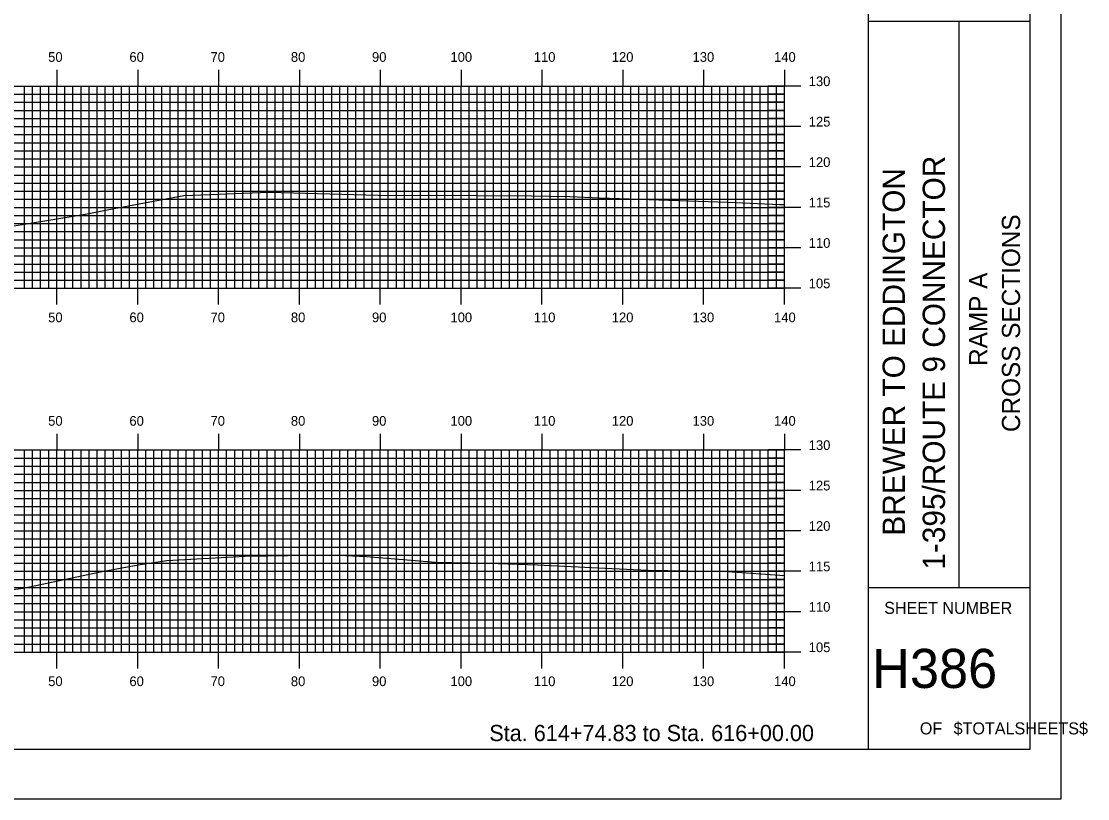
# Model space of a CAD drawing. Extents: x 844536 to 844879, y 363538 to 363758.
# Drawn here: x 844747.6 to 844879.5, y 363537.6 to 363633.7 of the extents above; entities that cross this region are included whole.
import ezdxf

# ---------------------------------------------------------------- set-up
doc = ezdxf.new("R2010")
doc.units = 0
for name, color, linetype in [('BORDER', 7, 'Continuous'), ('H_V ANNOTATION', 7, 'Continuous'), ('MAJOR', 7, 'Continuous'), ('MINOR', 7, 'Continuous'), ('PLOT BOUNDARY', 7, 'Continuous'), ('S_Roadway_Centerline', 7, 'Continuous')]:
    doc.layers.add(name, color=color, linetype=linetype)

msp = doc.modelspace()

# ---------------------------------------------------------------- linework, layer by layer
at = {"layer": 'BORDER'}
for p, q in [((844852.36, 363543.72), (844852.36, 363753.72)), ((844852.36, 363633.73), (844872.36, 363633.73)), ((844863.55, 363563.73), (844863.55, 363633.73)), ((844852.36, 363563.73), (844872.36, 363563.73))]:
    msp.add_line(p, q, dxfattribs=at)
msp.add_lwpolyline([(844552.36, 363543.72), (844872.36, 363543.72), (844872.36, 363753.72), (844552.36, 363753.72)], close=True, dxfattribs=at)
at = {"layer": 'MAJOR'}
for p, q in [((844751.96, 363627.73), (844751.96, 363625.72)), ((844761.96, 363627.73), (844761.96, 363625.72)), ((844771.96, 363627.73), (844771.96, 363625.72)), ((844781.96, 363627.73), (844781.96, 363625.72)), ((844791.96, 363627.73), (844791.96, 363625.72)), ((844801.96, 363627.73), (844801.96, 363625.72)), ((844811.96, 363627.73), (844811.96, 363625.72)), ((844821.96, 363627.73), (844821.96, 363625.72)), ((844831.96, 363627.73), (844831.96, 363625.72)), ((844841.96, 363627.73), (844841.96, 363625.72)), ((844561.96, 363625.72), (844841.96, 363625.72)), ((844561.96, 363625.72), (844841.96, 363625.72)), ((844751.96, 363600.72), (844751.96, 363625.72)), ((844761.96, 363600.72), (844761.96, 363625.72)), ((844771.96, 363600.72), (844771.96, 363625.72)), ((844781.96, 363600.72), (844781.96, 363625.72)), ((844791.96, 363600.72), (844791.96, 363625.72)), ((844801.96, 363600.72), (844801.96, 363625.72)), ((844811.96, 363600.72), (844811.96, 363625.72)), ((844821.96, 363600.72), (844821.96, 363625.72)), ((844831.96, 363600.72), (844831.96, 363625.72)), ((844843.97, 363625.72), (844839.96, 363625.72)), ((844841.96, 363600.72), (844841.96, 363625.72)), ((844841.96, 363600.72), (844841.96, 363625.72)), ((844561.96, 363620.72), (844841.96, 363620.72)), ((844843.97, 363620.72), (844839.96, 363620.72)), ((844561.96, 363615.72), (844841.96, 363615.72)), ((844843.97, 363615.72), (844839.96, 363615.72)), ((844561.96, 363610.72), (844841.96, 363610.72)), ((844843.97, 363610.72), (844839.96, 363610.72)), ((844561.96, 363605.72), (844841.96, 363605.72)), ((844843.97, 363605.72), (844839.96, 363605.72)), ((844561.96, 363600.72), (844841.96, 363600.72)), ((844561.96, 363600.72), (844841.96, 363600.72)), ((844751.96, 363598.72), (844751.96, 363600.72)), ((844761.96, 363598.72), (844761.96, 363600.72)), ((844771.96, 363598.72), (844771.96, 363600.72)), ((844781.96, 363598.72), (844781.96, 363600.72)), ((844791.96, 363598.72), (844791.96, 363600.72)), ((844801.96, 363598.72), (844801.96, 363600.72)), ((844811.96, 363598.72), (844811.96, 363600.72)), ((844821.96, 363598.72), (844821.96, 363600.72)), ((844831.96, 363598.72), (844831.96, 363600.72)), ((844843.97, 363600.72), (844839.96, 363600.72)), ((844841.96, 363598.72), (844841.96, 363600.72)), ((844751.96, 363582.73), (844751.96, 363580.72)), ((844761.96, 363582.73), (844761.96, 363580.72)), ((844771.96, 363582.73), (844771.96, 363580.72)), ((844781.96, 363582.73), (844781.96, 363580.72)), ((844791.96, 363582.73), (844791.96, 363580.72)), ((844801.96, 363582.73), (844801.96, 363580.72)), ((844811.96, 363582.73), (844811.96, 363580.72)), ((844821.96, 363582.73), (844821.96, 363580.72)), ((844831.96, 363582.73), (844831.96, 363580.72)), ((844841.96, 363582.73), (844841.96, 363580.72)), ((844561.96, 363580.72), (844841.96, 363580.72)), ((844561.96, 363580.72), (844841.96, 363580.72)), ((844751.96, 363555.72), (844751.96, 363580.72)), ((844761.96, 363555.72), (844761.96, 363580.72)), ((844771.96, 363555.72), (844771.96, 363580.72)), ((844781.96, 363555.72), (844781.96, 363580.72)), ((844791.96, 363555.72), (844791.96, 363580.72)), ((844801.96, 363555.72), (844801.96, 363580.72)), ((844811.96, 363555.72), (844811.96, 363580.72)), ((844821.96, 363555.72), (844821.96, 363580.72)), ((844831.96, 363555.72), (844831.96, 363580.72)), ((844843.97, 363580.72), (844839.96, 363580.72)), ((844841.96, 363555.72), (844841.96, 363580.72)), ((844841.96, 363555.72), (844841.96, 363580.72)), ((844561.96, 363575.72), (844841.96, 363575.72)), ((844843.97, 363575.72), (844839.96, 363575.72)), ((844561.96, 363570.72), (844841.96, 363570.72)), ((844843.97, 363570.72), (844839.96, 363570.72)), ((844561.96, 363565.72), (844841.96, 363565.72)), ((844843.97, 363565.72), (844839.96, 363565.72)), ((844561.96, 363560.72), (844841.96, 363560.72)), ((844843.97, 363560.72), (844839.96, 363560.72)), ((844561.96, 363555.72), (844841.96, 363555.72)), ((844561.96, 363555.72), (844841.96, 363555.72)), ((844751.96, 363553.72), (844751.96, 363555.72)), ((844761.96, 363553.72), (844761.96, 363555.72)), ((844771.96, 363553.72), (844771.96, 363555.72)), ((844781.96, 363553.72), (844781.96, 363555.72)), ((844791.96, 363553.72), (844791.96, 363555.72)), ((844801.96, 363553.72), (844801.96, 363555.72)), ((844811.96, 363553.72), (844811.96, 363555.72)), ((844821.96, 363553.72), (844821.96, 363555.72)), ((844831.96, 363553.72), (844831.96, 363555.72)), ((844843.97, 363555.72), (844839.96, 363555.72)), ((844841.96, 363553.72), (844841.96, 363555.72))]:
    msp.add_line(p, q, dxfattribs=at)
at = {"layer": 'MINOR'}
for p, q in [((844747.96, 363600.72), (844747.96, 363625.72)), ((844748.96, 363600.72), (844748.96, 363625.72)), ((844749.96, 363600.72), (844749.96, 363625.72)), ((844750.96, 363600.72), (844750.96, 363625.72)), ((844752.96, 363600.72), (844752.96, 363625.72)), ((844753.96, 363600.72), (844753.96, 363625.72)), ((844754.96, 363600.72), (844754.96, 363625.72)), ((844755.96, 363600.72), (844755.96, 363625.72)), ((844756.96, 363600.72), (844756.96, 363625.72)), ((844757.96, 363600.72), (844757.96, 363625.72)), ((844758.96, 363600.72), (844758.96, 363625.72)), ((844759.96, 363600.72), (844759.96, 363625.72)), ((844760.96, 363600.72), (844760.96, 363625.72)), ((844762.96, 363600.72), (844762.96, 363625.72)), ((844763.96, 363600.72), (844763.96, 363625.72)), ((844764.96, 363600.72), (844764.96, 363625.72)), ((844765.96, 363600.72), (844765.96, 363625.72)), ((844766.96, 363600.72), (844766.96, 363625.72)), ((844767.96, 363600.72), (844767.96, 363625.72)), ((844768.96, 363600.72), (844768.96, 363625.72)), ((844769.96, 363600.72), (844769.96, 363625.72)), ((844770.96, 363600.72), (844770.96, 363625.72)), ((844772.96, 363600.72), (844772.96, 363625.72)), ((844773.96, 363600.72), (844773.96, 363625.72)), ((844774.96, 363600.72), (844774.96, 363625.72)), ((844775.96, 363600.72), (844775.96, 363625.72)), ((844776.96, 363600.72), (844776.96, 363625.72)), ((844777.96, 363600.72), (844777.96, 363625.72)), ((844778.96, 363600.72), (844778.96, 363625.72)), ((844779.96, 363600.72), (844779.96, 363625.72)), ((844780.96, 363600.72), (844780.96, 363625.72)), ((844782.96, 363600.72), (844782.96, 363625.72)), ((844783.96, 363600.72), (844783.96, 363625.72)), ((844784.96, 363600.72), (844784.96, 363625.72)), ((844785.96, 363600.72), (844785.96, 363625.72)), ((844786.96, 363600.72), (844786.96, 363625.72)), ((844787.96, 363600.72), (844787.96, 363625.72)), ((844788.96, 363600.72), (844788.96, 363625.72)), ((844789.96, 363600.72), (844789.96, 363625.72)), ((844790.96, 363600.72), (844790.96, 363625.72)), ((844792.96, 363600.72), (844792.96, 363625.72)), ((844793.96, 363600.72), (844793.96, 363625.72)), ((844794.96, 363600.72), (844794.96, 363625.72)), ((844795.96, 363600.72), (844795.96, 363625.72)), ((844796.96, 363600.72), (844796.96, 363625.72)), ((844797.96, 363600.72), (844797.96, 363625.72)), ((844798.96, 363600.72), (844798.96, 363625.72)), ((844799.96, 363600.72), (844799.96, 363625.72)), ((844800.96, 363600.72), (844800.96, 363625.72)), ((844802.96, 363600.72), (844802.96, 363625.72)), ((844803.96, 363600.72), (844803.96, 363625.72)), ((844804.96, 363600.72), (844804.96, 363625.72)), ((844805.96, 363600.72), (844805.96, 363625.72)), ((844806.96, 363600.72), (844806.96, 363625.72)), ((844807.96, 363600.72), (844807.96, 363625.72)), ((844808.96, 363600.72), (844808.96, 363625.72)), ((844809.96, 363600.72), (844809.96, 363625.72)), ((844810.96, 363600.72), (844810.96, 363625.72)), ((844812.96, 363600.72), (844812.96, 363625.72)), ((844813.96, 363600.72), (844813.96, 363625.72)), ((844814.96, 363600.72), (844814.96, 363625.72)), ((844815.96, 363600.72), (844815.96, 363625.72)), ((844816.96, 363600.72), (844816.96, 363625.72)), ((844817.96, 363600.72), (844817.96, 363625.72)), ((844818.96, 363600.72), (844818.96, 363625.72)), ((844819.96, 363600.72), (844819.96, 363625.72)), ((844820.96, 363600.72), (844820.96, 363625.72)), ((844822.96, 363600.72), (844822.96, 363625.72)), ((844823.96, 363600.72), (844823.96, 363625.72)), ((844824.96, 363600.72), (844824.96, 363625.72)), ((844825.96, 363600.72), (844825.96, 363625.72)), ((844826.96, 363600.72), (844826.96, 363625.72)), ((844827.96, 363600.72), (844827.96, 363625.72)), ((844828.96, 363600.72), (844828.96, 363625.72)), ((844829.96, 363600.72), (844829.96, 363625.72)), ((844830.96, 363600.72), (844830.96, 363625.72)), ((844832.96, 363600.72), (844832.96, 363625.72)), ((844833.96, 363600.72), (844833.96, 363625.72)), ((844834.96, 363600.72), (844834.96, 363625.72)), ((844835.96, 363600.72), (844835.96, 363625.72)), ((844836.96, 363600.72), (844836.96, 363625.72)), ((844837.96, 363600.72), (844837.96, 363625.72)), ((844838.96, 363600.72), (844838.96, 363625.72)), ((844839.96, 363600.72), (844839.96, 363625.72)), ((844840.96, 363600.72), (844840.96, 363625.72)), ((844561.96, 363624.72), (844841.96, 363624.72)), ((844561.96, 363623.72), (844841.96, 363623.72)), ((844841.96, 363624.72), (844839.96, 363624.72)), ((844841.96, 363623.72), (844839.96, 363623.72)), ((844561.96, 363622.72), (844841.96, 363622.72)), ((844841.96, 363622.72), (844839.96, 363622.72)), ((844561.96, 363621.72), (844841.96, 363621.72)), ((844841.96, 363621.72), (844839.96, 363621.72)), ((844561.96, 363619.72), (844841.96, 363619.72)), ((844841.96, 363619.72), (844839.96, 363619.72)), ((844561.96, 363618.72), (844841.96, 363618.72)), ((844841.96, 363618.72), (844839.96, 363618.72)), ((844561.96, 363617.72), (844841.96, 363617.72)), ((844841.96, 363617.72), (844839.96, 363617.72)), ((844561.96, 363616.72), (844841.96, 363616.72)), ((844841.96, 363616.72), (844839.96, 363616.72)), ((844561.96, 363614.72), (844841.96, 363614.72)), ((844841.96, 363614.72), (844839.96, 363614.72)), ((844561.96, 363613.72), (844841.96, 363613.72)), ((844841.96, 363613.72), (844839.96, 363613.72)), ((844561.96, 363612.72), (844841.96, 363612.72)), ((844561.96, 363611.72), (844841.96, 363611.72)), ((844841.96, 363612.72), (844839.96, 363612.72)), ((844841.96, 363611.72), (844839.96, 363611.72)), ((844561.96, 363609.72), (844841.96, 363609.72)), ((844841.96, 363609.72), (844839.96, 363609.72)), ((844561.96, 363608.72), (844841.96, 363608.72)), ((844561.96, 363607.72), (844841.96, 363607.72)), ((844841.96, 363608.72), (844839.96, 363608.72)), ((844841.96, 363607.72), (844839.96, 363607.72)), ((844561.96, 363606.72), (844841.96, 363606.72)), ((844841.96, 363606.72), (844839.96, 363606.72)), ((844561.96, 363604.72), (844841.96, 363604.72)), ((844561.96, 363603.72), (844841.96, 363603.72)), ((844841.96, 363604.72), (844839.96, 363604.72)), ((844841.96, 363603.72), (844839.96, 363603.72)), ((844561.96, 363602.72), (844841.96, 363602.72)), ((844841.96, 363602.72), (844839.96, 363602.72)), ((844561.96, 363601.72), (844841.96, 363601.72)), ((844841.96, 363601.72), (844839.96, 363601.72)), ((844747.96, 363555.72), (844747.96, 363580.72)), ((844748.96, 363555.72), (844748.96, 363580.72)), ((844749.96, 363555.72), (844749.96, 363580.72)), ((844750.96, 363555.72), (844750.96, 363580.72)), ((844752.96, 363555.72), (844752.96, 363580.72)), ((844753.96, 363555.72), (844753.96, 363580.72)), ((844754.96, 363555.72), (844754.96, 363580.72)), ((844755.96, 363555.72), (844755.96, 363580.72)), ((844756.96, 363555.72), (844756.96, 363580.72)), ((844757.96, 363555.72), (844757.96, 363580.72)), ((844758.96, 363555.72), (844758.96, 363580.72)), ((844759.96, 363555.72), (844759.96, 363580.72)), ((844760.96, 363555.72), (844760.96, 363580.72)), ((844762.96, 363555.72), (844762.96, 363580.72)), ((844763.96, 363555.72), (844763.96, 363580.72)), ((844764.96, 363555.72), (844764.96, 363580.72)), ((844765.96, 363555.72), (844765.96, 363580.72)), ((844766.96, 363555.72), (844766.96, 363580.72)), ((844767.96, 363555.72), (844767.96, 363580.72)), ((844768.96, 363555.72), (844768.96, 363580.72)), ((844769.96, 363555.72), (844769.96, 363580.72)), ((844770.96, 363555.72), (844770.96, 363580.72)), ((844772.96, 363555.72), (844772.96, 363580.72)), ((844773.96, 363555.72), (844773.96, 363580.72)), ((844774.96, 363555.72), (844774.96, 363580.72)), ((844775.96, 363555.72), (844775.96, 363580.72)), ((844776.96, 363555.72), (844776.96, 363580.72)), ((844777.96, 363555.72), (844777.96, 363580.72)), ((844778.96, 363555.72), (844778.96, 363580.72)), ((844779.96, 363555.72), (844779.96, 363580.72)), ((844780.96, 363555.72), (844780.96, 363580.72)), ((844782.96, 363555.72), (844782.96, 363580.72)), ((844783.96, 363555.72), (844783.96, 363580.72)), ((844784.96, 363555.72), (844784.96, 363580.72)), ((844785.96, 363555.72), (844785.96, 363580.72)), ((844786.96, 363555.72), (844786.96, 363580.72)), ((844787.96, 363555.72), (844787.96, 363580.72)), ((844788.96, 363555.72), (844788.96, 363580.72)), ((844789.96, 363555.72), (844789.96, 363580.72)), ((844790.96, 363555.72), (844790.96, 363580.72)), ((844792.96, 363555.72), (844792.96, 363580.72)), ((844793.96, 363555.72), (844793.96, 363580.72)), ((844794.96, 363555.72), (844794.96, 363580.72)), ((844795.96, 363555.72), (844795.96, 363580.72)), ((844796.96, 363555.72), (844796.96, 363580.72)), ((844797.96, 363555.72), (844797.96, 363580.72)), ((844798.96, 363555.72), (844798.96, 363580.72)), ((844799.96, 363555.72), (844799.96, 363580.72)), ((844800.96, 363555.72), (844800.96, 363580.72)), ((844802.96, 363555.72), (844802.96, 363580.72)), ((844803.96, 363555.72), (844803.96, 363580.72)), ((844804.96, 363555.72), (844804.96, 363580.72)), ((844805.96, 363555.72), (844805.96, 363580.72)), ((844806.96, 363555.72), (844806.96, 363580.72)), ((844807.96, 363555.72), (844807.96, 363580.72)), ((844808.96, 363555.72), (844808.96, 363580.72)), ((844809.96, 363555.72), (844809.96, 363580.72)), ((844810.96, 363555.72), (844810.96, 363580.72)), ((844812.96, 363555.72), (844812.96, 363580.72)), ((844813.96, 363555.72), (844813.96, 363580.72)), ((844814.96, 363555.72), (844814.96, 363580.72)), ((844815.96, 363555.72), (844815.96, 363580.72)), ((844816.96, 363555.72), (844816.96, 363580.72)), ((844817.96, 363555.72), (844817.96, 363580.72)), ((844818.96, 363555.72), (844818.96, 363580.72)), ((844819.96, 363555.72), (844819.96, 363580.72)), ((844820.96, 363555.72), (844820.96, 363580.72)), ((844822.96, 363555.72), (844822.96, 363580.72)), ((844823.96, 363555.72), (844823.96, 363580.72)), ((844824.96, 363555.72), (844824.96, 363580.72)), ((844825.96, 363555.72), (844825.96, 363580.72)), ((844826.96, 363555.72), (844826.96, 363580.72)), ((844827.96, 363555.72), (844827.96, 363580.72)), ((844828.96, 363555.72), (844828.96, 363580.72)), ((844829.96, 363555.72), (844829.96, 363580.72)), ((844830.96, 363555.72), (844830.96, 363580.72)), ((844832.96, 363555.72), (844832.96, 363580.72)), ((844833.96, 363555.72), (844833.96, 363580.72)), ((844834.96, 363555.72), (844834.96, 363580.72)), ((844835.96, 363555.72), (844835.96, 363580.72)), ((844836.96, 363555.72), (844836.96, 363580.72)), ((844837.96, 363555.72), (844837.96, 363580.72)), ((844838.96, 363555.72), (844838.96, 363580.72)), ((844839.96, 363555.72), (844839.96, 363580.72)), ((844840.96, 363555.72), (844840.96, 363580.72)), ((844561.96, 363579.72), (844841.96, 363579.72)), ((844561.96, 363578.72), (844841.96, 363578.72)), ((844841.96, 363579.72), (844839.96, 363579.72)), ((844841.96, 363578.72), (844839.96, 363578.72)), ((844561.96, 363577.72), (844841.96, 363577.72)), ((844841.96, 363577.72), (844839.96, 363577.72)), ((844561.96, 363576.72), (844841.96, 363576.72)), ((844841.96, 363576.72), (844839.96, 363576.72)), ((844561.96, 363574.72), (844841.96, 363574.72)), ((844841.96, 363574.72), (844839.96, 363574.72)), ((844561.96, 363573.72), (844841.96, 363573.72)), ((844841.96, 363573.72), (844839.96, 363573.72)), ((844561.96, 363572.72), (844841.96, 363572.72)), ((844841.96, 363572.72), (844839.96, 363572.72)), ((844561.96, 363571.72), (844841.96, 363571.72)), ((844841.96, 363571.72), (844839.96, 363571.72)), ((844561.96, 363569.72), (844841.96, 363569.72)), ((844841.96, 363569.72), (844839.96, 363569.72)), ((844561.96, 363568.72), (844841.96, 363568.72)), ((844841.96, 363568.72), (844839.96, 363568.72)), ((844561.96, 363567.72), (844841.96, 363567.72)), ((844841.96, 363567.72), (844839.96, 363567.72)), ((844561.96, 363566.72), (844841.96, 363566.72)), ((844841.96, 363566.72), (844839.96, 363566.72)), ((844561.96, 363564.72), (844841.96, 363564.72)), ((844841.96, 363564.72), (844839.96, 363564.72)), ((844561.96, 363563.72), (844841.96, 363563.72)), ((844841.96, 363563.72), (844839.96, 363563.72)), ((844561.96, 363562.72), (844841.96, 363562.72)), ((844561.96, 363561.72), (844841.96, 363561.72)), ((844841.96, 363562.72), (844839.96, 363562.72)), ((844841.96, 363561.72), (844839.96, 363561.72)), ((844561.96, 363559.72), (844841.96, 363559.72)), ((844841.96, 363559.72), (844839.96, 363559.72)), ((844561.96, 363558.72), (844841.96, 363558.72)), ((844561.96, 363557.72), (844841.96, 363557.72)), ((844841.96, 363558.72), (844839.96, 363558.72)), ((844841.96, 363557.72), (844839.96, 363557.72)), ((844561.96, 363556.72), (844841.96, 363556.72)), ((844841.96, 363556.72), (844839.96, 363556.72))]:
    msp.add_line(p, q, dxfattribs=at)
at = {"layer": 'PLOT BOUNDARY'}
msp.add_lwpolyline([(844536.18, 363537.6), (844876.18, 363537.6), (844876.18, 363757.6), (844536.18, 363757.6)], close=True, dxfattribs=at)
at = {"layer": 'S_Roadway_Centerline'}
for points in [[(844743.63, 363607.93), (844754.24, 363609.66), (844755.7, 363609.93), (844758.39, 363610.44), (844767.67, 363612.19), (844778.22, 363612.59), (844793.17, 363612.21), (844797.08, 363612.23), (844810.65, 363612.13), (844815.4, 363612.08), (844819.09, 363611.92), (844834.95, 363611.37), (844841.39, 363611.09), (844841.96, 363611.07)], [(844744.34, 363563.2), (844747.8, 363563.65), (844757.37, 363565.64), (844762.01, 363566.51), (844765.56, 363567.07), (844775.24, 363567.61), (844785.92, 363567.76), (844790.27, 363567.55), (844798.78, 363566.85), (844805.3, 363566.74), (844811.41, 363566.52), (844820.59, 363566.05), (844825.08, 363565.87), (844834.92, 363565.69), (844841.96, 363565.2)]]:
    msp.add_lwpolyline(points, dxfattribs=at)

# ---------------------------------------------------------------- texts
at = {"layer": 'BORDER'}
for s, height, p in [('1-395/ROUTE 9 CONNECTOR', 2.7557, (844861.81, 363565.92)), ('BREWER TO EDDINGTON', 2.7557, (844856.85, 363570.13)), ('CROSS SECTIONS', 2.25, (844871.1, 363582.94)), ('RAMP A', 2.25, (844867.05, 363591.12))]:
    msp.add_text(s, height=height, rotation=90, dxfattribs=at).set_placement(p)
for s, height, p in [('SHEET NUMBER', 1.4905, (844854.29, 363560.45)), ('H386', 4.839, (844852.8, 363551.29)), ('OF', 1.491, (844858.7, 363545.55)), ('$TOTALSHEETS$', 1.4905, (844862.88, 363545.55))]:
    msp.add_text(s, height=height, dxfattribs=at).set_placement(p)
at = {"layer": 'H_V ANNOTATION'}
for s, height, p in [('50', 1.2, (844750.89, 363628.72)), ('60', 1.2, (844760.94, 363628.72)), ('70', 1.2, (844770.97, 363628.72)), ('80', 1.2, (844780.91, 363628.72)), ('90', 1.2, (844790.94, 363628.72)), ('100', 1.2, (844800.65, 363628.72)), ('110', 1.2, (844810.95, 363628.72)), ('120', 1.2, (844820.6, 363628.72)), ('130', 1.2, (844830.59, 363628.72)), ('140', 1.2, (844840.67, 363628.72)), ('130', 1.2, (844844.96, 363625.72)), ('125', 1.2, (844844.96, 363620.72)), ('120', 1.2, (844844.96, 363615.72)), ('115', 1.2, (844844.96, 363610.72)), ('110', 1.2, (844844.96, 363605.72)), ('105', 1.2, (844844.96, 363600.72)), ('50', 1.2, (844750.89, 363596.52)), ('60', 1.2, (844760.94, 363596.52)), ('70', 1.2, (844770.97, 363596.52)), ('80', 1.2, (844780.91, 363596.52)), ('90', 1.2, (844790.94, 363596.52)), ('100', 1.2, (844800.65, 363596.52)), ('110', 1.2, (844810.95, 363596.52)), ('120', 1.2, (844820.6, 363596.52)), ('130', 1.2, (844830.59, 363596.52)), ('140', 1.2, (844840.67, 363596.52)), ('50', 1.2, (844750.89, 363583.72)), ('60', 1.2, (844760.94, 363583.72)), ('70', 1.2, (844770.97, 363583.72)), ('80', 1.2, (844780.91, 363583.72)), ('90', 1.2, (844790.94, 363583.72)), ('100', 1.2, (844800.65, 363583.72)), ('110', 1.2, (844810.95, 363583.72)), ('120', 1.2, (844820.6, 363583.72)), ('130', 1.2, (844830.59, 363583.72)), ('140', 1.2, (844840.67, 363583.72)), ('130', 1.2, (844844.96, 363580.72)), ('125', 1.2, (844844.96, 363575.72)), ('120', 1.2, (844844.96, 363570.72)), ('115', 1.2, (844844.96, 363565.72)), ('110', 1.2, (844844.96, 363560.72)), ('105', 1.2, (844844.96, 363555.72)), ('50', 1.2, (844750.89, 363551.52)), ('60', 1.2, (844760.94, 363551.52)), ('70', 1.2, (844770.97, 363551.52)), ('80', 1.2, (844780.91, 363551.52)), ('90', 1.2, (844790.94, 363551.52)), ('100', 1.2, (844800.65, 363551.52)), ('110', 1.2, (844810.95, 363551.52)), ('120', 1.2, (844820.6, 363551.52)), ('130', 1.2, (844830.59, 363551.52)), ('140', 1.2, (844840.67, 363551.52)), ('Sta. 614+74.83 to Sta. 616+00.00', 2.0004, (844805.45, 363544.72))]:
    msp.add_text(s, height=height, dxfattribs=at).set_placement(p)

doc.saveas('drawing.dxf')
